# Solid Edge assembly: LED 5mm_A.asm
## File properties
Title: LED 5mm
Author: NMH
Template: Iso Metric Assembly.asm
Last saved by: NMH
Revision: 5
Application: Solid Edge
Username: NMH
Document Number: LED
Revision: A
Rev B: B
Rev B Text: -
Rev B Date: -
Rev C: C
Rev C Text: -
Rev C Date: -
Rev D: D
Rev D Text: -
Rev D Date: -
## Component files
LED Negiative Leg_A.par
LED Positive Leg_A.par
LED Bulb_A.par
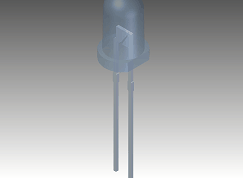
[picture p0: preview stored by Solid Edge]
